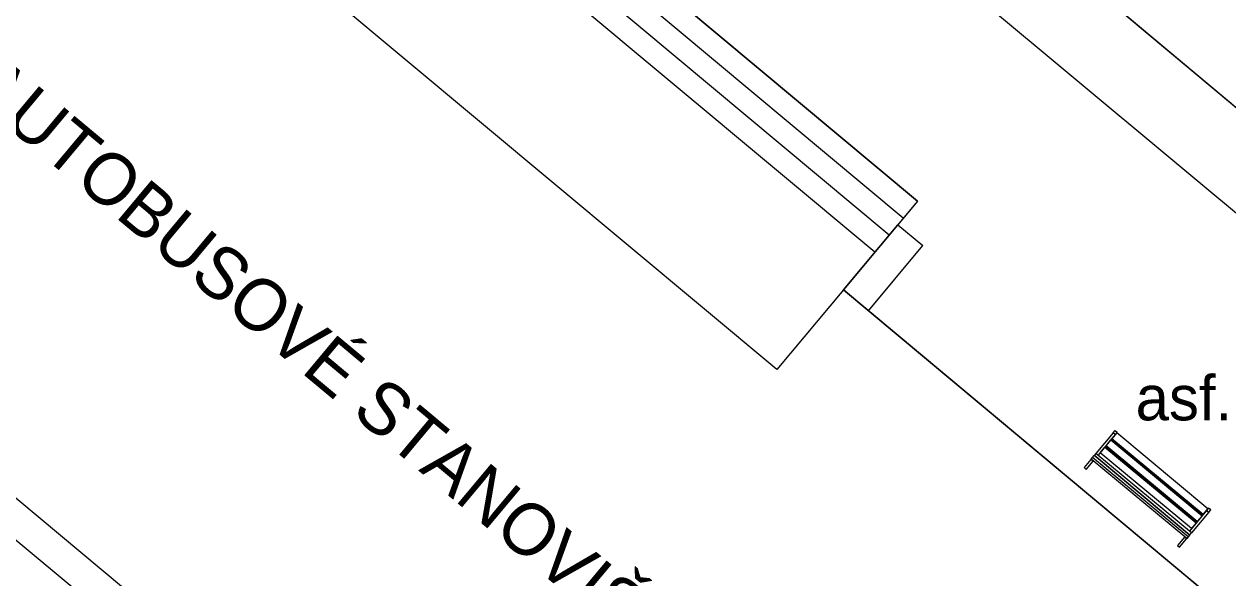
# Model space of a CAD drawing. Extents: x -438200 to -437954, y -1133133 to -1132850.
# Drawn here: x -438114.64 to -438097.2, y -1132995.08 to -1132987.05 of the extents above; entities that cross this region are included whole.
import ezdxf

# ---------------------------------------------------------------- set-up
doc = ezdxf.new("R2010")
doc.units = 0
for name, color, linetype in [('MOBILIÁŘ', 7, 'Continuous'), ('Vrstva 1', 7, 'Continuous'), ('Vrstva 10', 7, 'Continuous'), ('Vrstva 11', 7, 'Continuous'), ('Vrstva 40', 7, 'Continuous'), ('Vrstva 5', 7, 'Continuous'), ('Vrstva 50', 7, 'Continuous'), ('Vrstva 55', 7, 'Continuous')]:
    doc.layers.add(name, color=color, linetype=linetype)

# ---------------------------------------------------------------- blocks, each defined once
blk = doc.blocks.new('A$C6FF56919')
at = {"layer": 'Vrstva 1'}
for p, q in [((-17605, 5482), (-17605, 7031)), ((-401, 7031), (-401, 5482)), ((0, 7031), (-401, 7031)), ((0, 5482), (0, 7031)), ((-18000, 5423), (-18000, 5482)), ((-18000, 5482), (-17605, 5482)), ((-18000, 5423), (0, 5423)), ((-18000, 5108), (-18000, 5423)), ((-17605, 5423), (-17605, 5482)), ((-401, 5482), (0, 5482)), ((-401, 5423), (-401, 5482)), ((0, 5423), (0, 5482)), ((0, 5423), (0, 5108)), ((-18000, 5108), (0, 5108)), ((-18000, 4771), (-18000, 5108)), ((-18000, 4771), (0, 4771)), ((-18000, 4707), (-18000, 4771)), ((0, 4707), (-18000, 4707)), ((-18000, 4707), (-18000, 4365)), ((-18000, 459), (-18000, 4365)), ((-18000, 4365), (0, 4365)), ((-17605, 459), (-17605, 4365)), ((-17605, 3703), (-17594, 3703)), ((-17594, 2805), (-17594, 3895)), ((-401, 3703), (-411, 3703)), ((-401, 459), (-401, 4365)), ((0, 5108), (0, 4771)), ((0, 4771), (0, 4707)), ((0, 4365), (0, 4707)), ((0, 459), (0, 4365)), ((-17605, 2907), (-17594, 2907)), ((-17605, 2901), (-17594, 2901)), ((-17605, 2410), (-17594, 2410)), ((-411, 2805), (-17594, 2805)), ((-17594, 2805), (-17594, 2762)), ((-17594, 2762), (-411, 2762)), ((-17594, 2575), (-411, 2575)), ((-17594, 1475), (-17594, 2575)), ((-9200, 2575), (-9200, 2762)), ((-8799, 2575), (-8799, 2762)), ((-401, 2907), (-411, 2907)), ((-401, 2901), (-411, 2901)), ((-411, 2762), (-411, 2805)), ((-411, 2575), (-411, 1475)), ((-401, 2410), (-411, 2410)), ((-18000, 459), (-18000, 0)), ((-17605, 459), (-18000, 459)), ((-18000, 0), (-17605, 0)), ((-17605, 1608), (-17594, 1608)), ((-17605, 1608), (-17594, 1608)), ((-17605, 1106), (-17594, 1106)), ((-17605, 1106), (-17594, 1106)), ((-17605, 0), (-17605, 459)), ((-17605, 305), (-17594, 305)), ((-17594, 1459), (-17594, 1475)), ((-17594, 1475), (-411, 1475)), ((-411, 1459), (-17594, 1459)), ((-17594, 1245), (-17594, 1256)), ((-17594, 1256), (-411, 1256)), ((-17594, 1245), (-17594, 144)), ((-411, 1245), (-17594, 1245)), ((-17594, 144), (-411, 144)), ((-9200, 1256), (-9200, 1459)), ((-8800, 1256), (-8800, 1459)), ((-401, 1608), (-411, 1608)), ((-401, 1608), (-411, 1608)), ((-411, 1475), (-411, 1459)), ((-411, 1256), (-411, 1245)), ((-411, 144), (-411, 1245)), ((-401, 1106), (-411, 1106)), ((-401, 1106), (-411, 1106)), ((-401, 305), (-411, 305)), ((-401, 459), (0, 459)), ((-401, 0), (-401, 459)), ((0, 0), (-401, 0)), ((0, 459), (0, 0))]:
    blk.add_line(p, q, dxfattribs=at)
for points in [[(-17605, 7031), (-18000, 7031), (-18000, 5482)], [(-17594, 3895), (-411, 3895), (-411, 2805)]]:
    blk.add_lwpolyline(points, dxfattribs=at)

msp = doc.modelspace()

# ---------------------------------------------------------------- linework, layer by layer
at = {"layer": 'Vrstva 1'}
for p, q in [((-438101.21, -1132984.8), (-438075.914, -1133005.992)), ((-438101.21, -1132984.8), (-438075.914, -1133005.992)), ((-438105.902, -1132987.364), (-438105.902, -1132987.364)), ((-438107.57, -1132988.841), (-438107.57, -1132988.841)), ((-438101.62, -1132990.259), (-438101.62, -1132990.259)), ((-438102.771, -1132990.9), (-438102.771, -1132990.9)), ((-438104.41, -1132991.493), (-438104.41, -1132991.493))]:
    msp.add_line(p, q, dxfattribs=at)
at = {"layer": 'Vrstva 10'}
msp.add_lwpolyline([(-438136.916, -1132976.04), (-438130.815, -1132968.777), (-438110.909, -1132985.383), (-438109.206, -1132983.342), (-438101.698, -1132989.616), (-438102.771, -1132990.9), (-438091.189, -1133000.578), (-438097.908, -1133008.583)], close=True, dxfattribs=at)
msp.add_lwpolyline([(-438136.916, -1132976.04), (-438130.815, -1132968.777), (-438110.909, -1132985.383), (-438109.206, -1132983.342), (-438101.698, -1132989.616), (-438102.771, -1132990.9), (-438091.189, -1133000.578), (-438097.908, -1133008.583)], close=True, dxfattribs=at)
msp.add_lwpolyline([(-438106.458, -1132981.967), (-438090.957, -1132994.89), (-438086.882, -1132998.283), (-438085.153, -1132999.203), (-438079.851, -1133001.541), (-438076.272, -1133002.948)], dxfattribs=at)
at = {"layer": 'Vrstva 11'}
for p, q in [((-438101.903, -1132989.862), (-438109.125, -1132983.827)), ((-438102.108, -1132990.107), (-438109.33, -1132984.072)), ((-438102.314, -1132990.353), (-438109.536, -1132984.318)), ((-438102.771, -1132990.9), (-438101.982, -1132989.956)), ((-438102.409, -1132991.203), (-438101.62, -1132990.259))]:
    msp.add_line(p, q, dxfattribs=at)
for points in [[(-438101.698, -1132989.616), (-438109.206, -1132983.342), (-438109.43, -1132983.611)], [(-438101.698, -1132989.616), (-438101.982, -1132989.956)], [(-438101.982, -1132989.956), (-438101.62, -1132990.259)]]:
    msp.add_lwpolyline(points, dxfattribs=at)
at = {"layer": 'Vrstva 5'}
for p, q in [((-438103.737, -1132992.056), (-438110.959, -1132986.021)), ((-438102.771, -1132990.9), (-438103.737, -1132992.056)), ((-438091.189, -1133000.578), (-438102.771, -1132990.9)), ((-438116.463, -1132992.491), (-438111.878, -1132996.316))]:
    msp.add_line(p, q, dxfattribs=at)
at = {"layer": 'Vrstva 50'}
msp.add_lwpolyline([(-438098.32, -1132981.35), (-438073.025, -1133002.541), (-438075.915, -1133005.991), (-438101.21, -1132984.8)], close=True, dxfattribs=at)
msp.add_lwpolyline([(-438098.32, -1132981.35), (-438073.025, -1133002.541), (-438075.915, -1133005.991), (-438101.21, -1132984.8)], close=True, dxfattribs=at)

# ---------------------------------------------------------------- block references
at = {"layer": 'MOBILIÁŘ', "xscale": 0.0001, "yscale": 0.00010000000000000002, "rotation": 140.22668670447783}
msp.add_blockref('A$C6FF56919', (-438098.834, -1132992.936), dxfattribs=at)

# ---------------------------------------------------------------- texts
at = {"layer": 'Vrstva 40'}
msp.add_text('asf.', height=0.65, dxfattribs=at).set_placement((-438098.539, -1132992.791))
at = {"layer": 'Vrstva 55'}
msp.add_text('AUTOBUSOVÉ STANOVIŠTE', height=0.74999, rotation=320.1027, dxfattribs=at).set_placement((-438115.474, -1132988.046))

doc.saveas('drawing.dxf')
